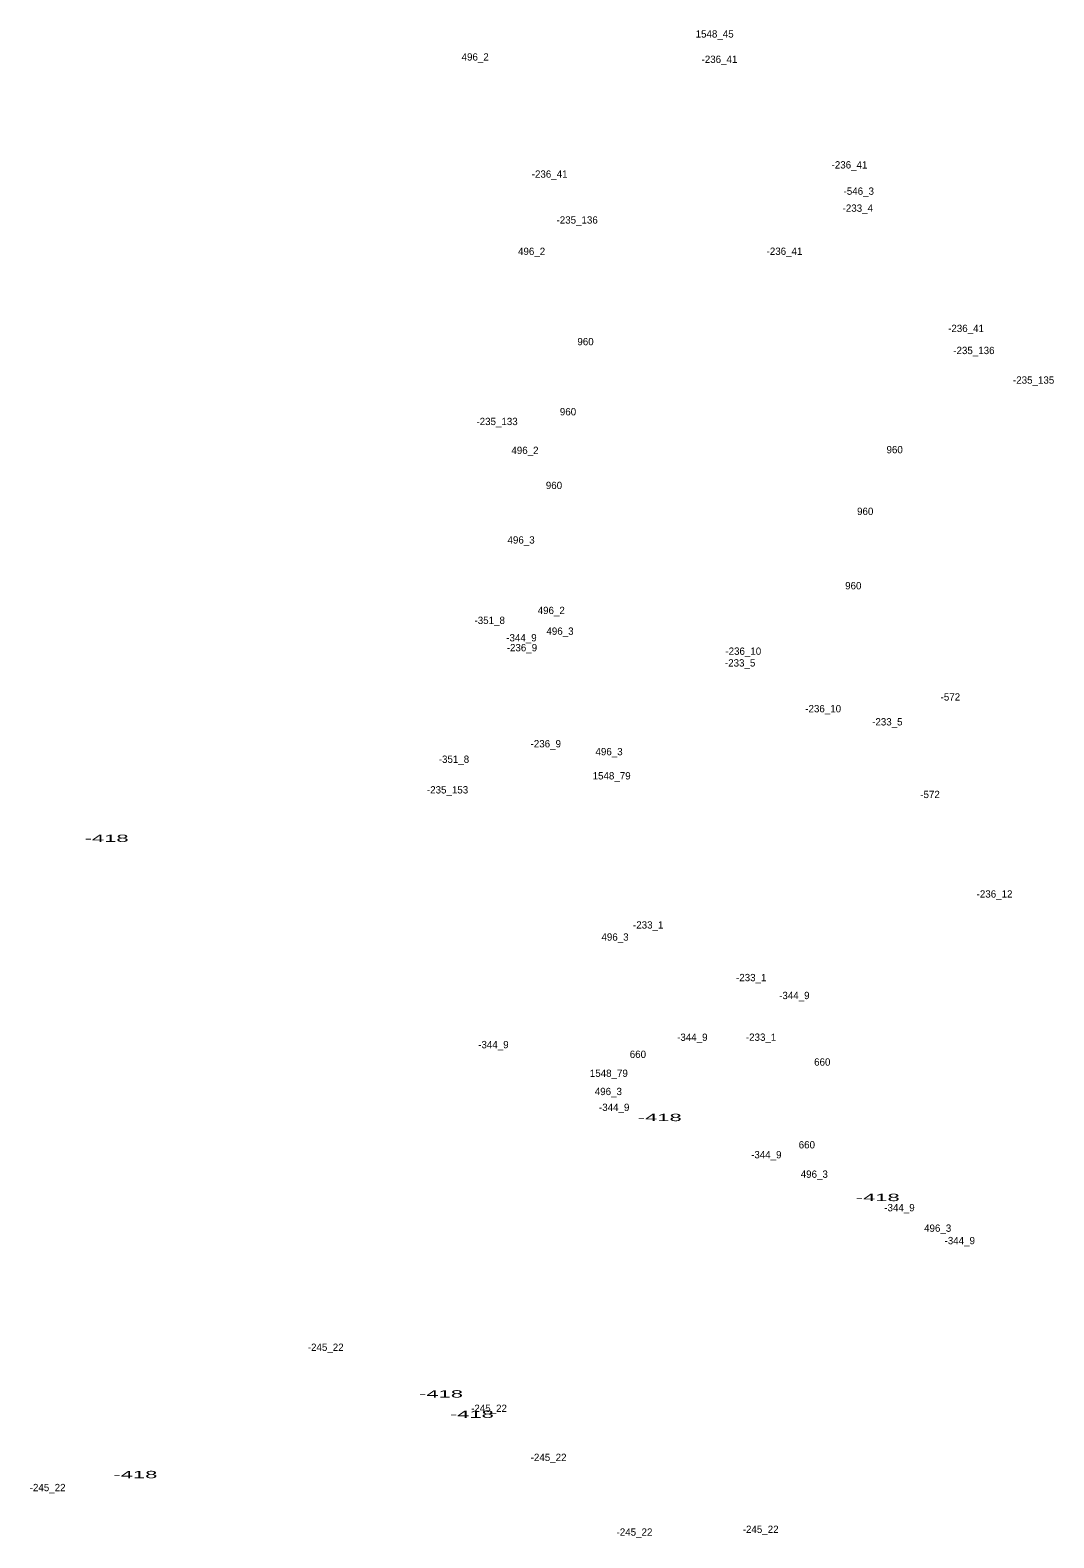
# Model space of a CAD drawing. Extents: x -660434 to -656144, y -997850 to -994016.
# Drawn here: x -659494 to -658933, y -996962 to -996136 of the extents above; entities that cross this region are included whole.
import ezdxf
from ezdxf.enums import TextEntityAlignment as Align

# ---------------------------------------------------------------- set-up
doc = ezdxf.new("R2010")
doc.units = 0
doc.header["$LTSCALE"] = 1.6
doc.layers.add('24', color=7, linetype='Continuous')

msp = doc.modelspace()

# ---------------------------------------------------------------- texts
at = {"layer": '24'}
for s, p in [('1548_45', (-659119.027, -996140.4)), ('496_2', (-659250.21, -996153)), ('-236_41', (-659116.385, -996154.29)), ('-236_41', (-659045.145, -996212.1)), ('-236_41', (-659209.415, -996217.14)), ('-546_3', (-659040.062, -996226.49)), ('-233_4', (-659040.597, -996235.8)), ('-235_136', (-659194.351, -996242.28)), ('496_2', (-659219.3, -996259.47)), ('-236_41', (-659080.765, -996259.4)), ('-236_41', (-658981.305, -996301.65)), ('960', (-659189.762, -996308.88)), ('-235_136', (-658977.001, -996313.73)), ('-235_135', (-658944.275, -996329.94)), ('960', (-659199.362, -996347.29)), ('-235_133', (-659238.225, -996352.61)), ('496_2', (-659222.94, -996368.43)), ('960', (-659020.412, -996368.04)), ('960', (-659207.042, -996387.63)), ('960', (-659036.542, -996401.84)), ('496_3', (-659225.06, -996417.49)), ('960', (-659043.072, -996442.56)), ('496_2', (-659208.54, -996456.09)), ('-351_8', (-659242.246, -996461.51)), ('496_3', (-659203.74, -996467.43)), ('-344_9', (-659224.866, -996471.05)), ('-236_9', (-659224.593, -996476.47)), ('-236_10', (-659103.335, -996478.39)), ('-233_5', (-659105.062, -996484.82)), ('-572', (-658989.891, -996503.46)), ('-236_10', (-659059.565, -996509.89)), ('-233_5', (-659024.422, -996517.09)), ('-236_9', (-659211.533, -996529.1)), ('496_3', (-659176.86, -996533.4)), ('-351_8', (-659261.836, -996537.57)), ('1548_79', (-659175.453, -996546.65)), ('-235_153', (-659265.345, -996554.33)), ('-572', (-659001.031, -996556.86)), ('-236_12', (-658965.691, -996611.35)), ('-233_1', (-659155.426, -996628.32)), ('496_3', (-659173.6, -996634.93)), ('-233_1', (-659098.976, -996657.13)), ('-344_9', (-659075.366, -996666.94)), ('-344_9', (-659131.246, -996689.81)), ('-233_1', (-659093.596, -996689.78)), ('-344_9', (-659240.226, -996693.84)), ('660', (-659161.062, -996699.15)), ('660', (-659060.062, -996703.37)), ('1548_79', (-659176.983, -996709.53)), ('496_3', (-659177.25, -996719.5)), ('-344_9', (-659174.056, -996728.18)), ('660', (-659068.512, -996748.7)), ('-344_9', (-659090.726, -996754.11)), ('496_3', (-659064.44, -996764.78)), ('-344_9', (-659017.766, -996783.12)), ('496_3', (-658996.85, -996794.35)), ('-344_9', (-658984.746, -996801.17)), ('-245_22', (-659332.096, -996859.57)), ('-245_22', (-659242.626, -996892.99)), ('-245_22', (-659209.986, -996919.88)), ('-245_22', (-659484.436, -996936.4)), ('-245_22', (-659162.936, -996960.79)), ('-245_22', (-659093.816, -996959.26))]:
    msp.add_text(s, height=4, dxfattribs=at).set_placement(p, align=Align.CENTER)
at = {"layer": '24', "width": 2.25}
for p in [(-659452.106, -996580.87), (-659149.116, -996733.75), (-659029.686, -996777.54), (-659268.926, -996885.11), (-659252.036, -996896.25), (-659436.366, -996929.29)]:
    msp.add_text('-418', height=4, dxfattribs=at).set_placement(p, align=Align.CENTER)

doc.saveas('drawing.dxf')
